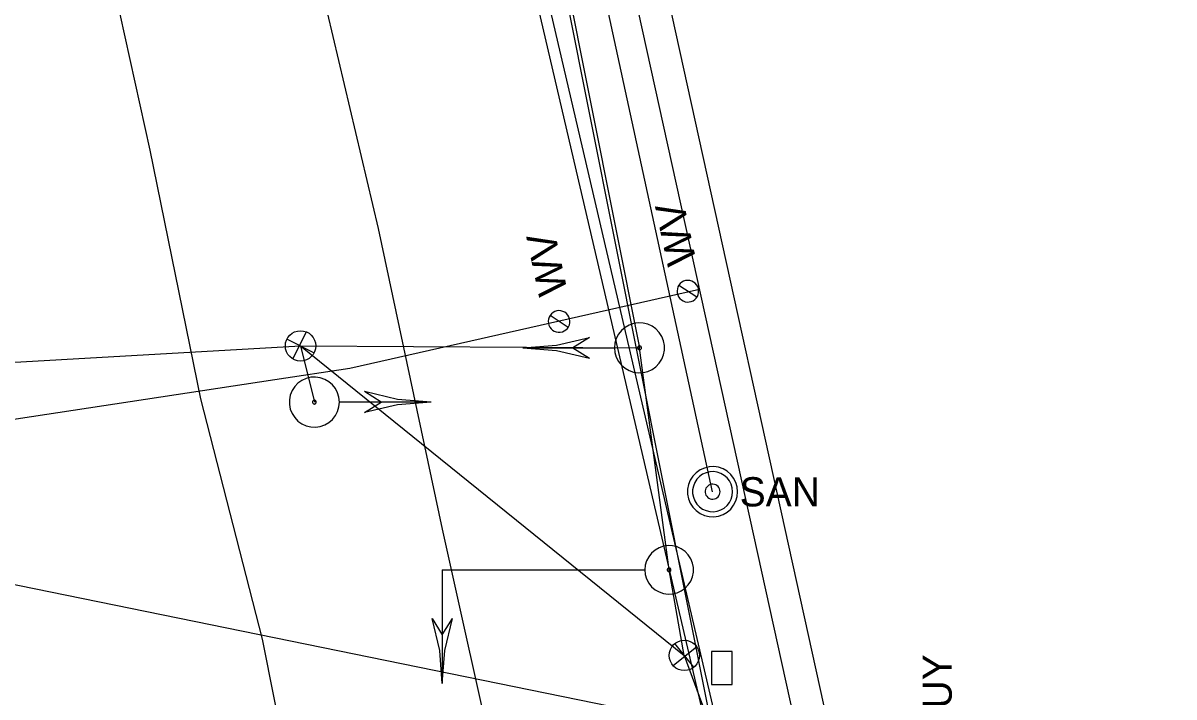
# Model space of a CAD drawing. Extents: x 596028 to 606371, y 330010 to 403088.
# Drawn here: x 604712 to 604863.7, y 339410.5 to 339499.3 of the extents above; entities that cross this region are included whole.
import ezdxf

# ---------------------------------------------------------------- set-up
doc = ezdxf.new("R2010")
doc.units = 0
for name, color, linetype in [('E_SIG', 7, 'Continuous'), ('E_SIG_Conduit', 7, 'Continuous'), ('E_UTL_E_UG', 7, 'Continuous'), ('E_UTL_EGuyWire', 7, 'Continuous'), ('E_UTL_FO_MH', 7, 'Continuous'), ('E_UTL_FO_UG', 7, 'Continuous'), ('E_UTL_G_UG', 7, 'Continuous'), ('E_UTL_Overhead', 7, 'Continuous'), ('E_UTL_SAN_MH', 7, 'Continuous'), ('E_UTL_SAN_UG', 7, 'Continuous'), ('E_UTL_SAN_UG_MMSD', 7, 'Continuous'), ('E_UTL_W', 7, 'Continuous'), ('E_UTL_W_UG', 7, 'Continuous')]:
    doc.layers.add(name, color=color, linetype=linetype)

# ---------------------------------------------------------------- blocks, each defined once
blk = doc.blocks.new('_U330')
at = {"layer": 'E_SIG'}
for p, q in [((0, 6.1), (0, -6.1)), ((-6.09, 0.4), (6.1, 0.4))]:
    blk.add_line(p, q, dxfattribs=at)
blk.add_circle((0, 0.01), 6.1, dxfattribs=at)
blk = doc.blocks.new('_U331')
at = {"layer": 'E_SIG'}
for p, q in [((0, 6.1), (0, -6.1)), ((-6.09, 0.4), (6.1, 0.4))]:
    blk.add_line(p, q, dxfattribs=at)
blk.add_circle((0, 0.01), 6.1, dxfattribs=at)

msp = doc.modelspace()

# ---------------------------------------------------------------- linework, layer by layer
at = {"layer": 'E_SIG'}
for points in [[(604789.97, 339456.48), (604790.03, 339455.86), (604790.21, 339455.26), (604790.49, 339454.7), (604790.88, 339454.2), (604791.36, 339453.79), (604791.9, 339453.48), (604792.49, 339453.27), (604793.11, 339453.19), (604793.74, 339453.22), (604794.35, 339453.36), (604794.92, 339453.62), (604795.43, 339453.99), (604795.86, 339454.44), (604796.2, 339454.97), (604796.44, 339455.55), (604796.55, 339456.17), (604796.55, 339456.8), (604796.44, 339457.41), (604796.2, 339457.99), (604795.86, 339458.52), (604795.43, 339458.98), (604794.92, 339459.34), (604794.35, 339459.6), (604793.74, 339459.75), (604793.11, 339459.78), (604792.49, 339459.69), (604791.9, 339459.48), (604791.36, 339459.17), (604790.88, 339458.76), (604790.49, 339458.27), (604790.21, 339457.71), (604790.03, 339457.11), (604789.97, 339456.48)], [(604777.87, 339456.48), (604782.32, 339456.83), (604786.67, 339457.86)], [(604786.67, 339457.85), (604784.47, 339456.48)], [(604748.6, 339456.73), (604750.42, 339449.33)], [(604777.87, 339456.48), (604789.91, 339456.48)], [(604777.87, 339456.48), (604782.32, 339456.14), (604786.67, 339455.11)], [(604784.47, 339456.48), (604786.67, 339455.11)], [(604793.02, 339456.48), (604793.02, 339456.43), (604793.04, 339456.39), (604793.06, 339456.35), (604793.09, 339456.31), (604793.12, 339456.28), (604793.16, 339456.25), (604793.21, 339456.24), (604793.26, 339456.23), (604793.31, 339456.23), (604793.35, 339456.24), (604793.4, 339456.26), (604793.43, 339456.29), (604793.47, 339456.33), (604793.49, 339456.37), (604793.51, 339456.41), (604793.52, 339456.46), (604793.52, 339456.51), (604793.51, 339456.55), (604793.49, 339456.6), (604793.47, 339456.64), (604793.43, 339456.67), (604793.4, 339456.7), (604793.35, 339456.72), (604793.31, 339456.73), (604793.26, 339456.73), (604793.21, 339456.73), (604793.16, 339456.71), (604793.12, 339456.69), (604793.09, 339456.66), (604793.06, 339456.62), (604793.04, 339456.58), (604793.02, 339456.53), (604793.02, 339456.48)], [(604753.72, 339449.33), (604753.66, 339449.96), (604753.48, 339450.56), (604753.2, 339451.11), (604752.81, 339451.61), (604752.34, 339452.02), (604751.79, 339452.33), (604751.2, 339452.54), (604750.58, 339452.63), (604749.95, 339452.6), (604749.34, 339452.45), (604748.77, 339452.19), (604748.26, 339451.82), (604747.83, 339451.37), (604747.49, 339450.84), (604747.25, 339450.26), (604747.14, 339449.64), (604747.14, 339449.02), (604747.25, 339448.4), (604747.49, 339447.82), (604747.83, 339447.29), (604748.26, 339446.84), (604748.77, 339446.47), (604749.34, 339446.21), (604749.95, 339446.06), (604750.58, 339446.03), (604751.2, 339446.12), (604751.79, 339446.33), (604752.34, 339446.64), (604752.81, 339447.05), (604753.2, 339447.55), (604753.48, 339448.1), (604753.66, 339448.71), (604753.72, 339449.33)], [(604750.67, 339449.33), (604750.67, 339449.38), (604750.66, 339449.42), (604750.63, 339449.47), (604750.6, 339449.5), (604750.57, 339449.54), (604750.53, 339449.56), (604750.48, 339449.58), (604750.43, 339449.58), (604750.39, 339449.58), (604750.34, 339449.57), (604750.3, 339449.55), (604750.26, 339449.52), (604750.22, 339449.49), (604750.2, 339449.45), (604750.18, 339449.4), (604750.17, 339449.35), (604750.17, 339449.31), (604750.18, 339449.26), (604750.2, 339449.21), (604750.22, 339449.17), (604750.26, 339449.14), (604750.3, 339449.11), (604750.34, 339449.09), (604750.39, 339449.08), (604750.43, 339449.08), (604750.48, 339449.09), (604750.53, 339449.1), (604750.57, 339449.13), (604750.6, 339449.16), (604750.63, 339449.19), (604750.66, 339449.24), (604750.67, 339449.28), (604750.67, 339449.33)], [(604765.82, 339449.33), (604753.78, 339449.33)], [(604765.82, 339449.33), (604761.37, 339449.68), (604757.02, 339450.71)], [(604759.22, 339449.33), (604757.02, 339450.71)], [(604765.82, 339449.33), (604761.37, 339448.98), (604757.02, 339447.96)], [(604757.02, 339447.96), (604759.22, 339449.33)], [(604793.97, 339427.23), (604794.02, 339426.62), (604794.2, 339426.04), (604794.48, 339425.5), (604794.85, 339425.02), (604795.31, 339424.62), (604795.84, 339424.32), (604796.41, 339424.12), (604797.02, 339424.03), (604797.63, 339424.06), (604798.22, 339424.2), (604798.77, 339424.46), (604799.27, 339424.81), (604799.69, 339425.25), (604800.02, 339425.76), (604800.24, 339426.33), (604800.36, 339426.93), (604800.36, 339427.54), (604800.24, 339428.13), (604800.02, 339428.7), (604799.69, 339429.21), (604799.27, 339429.65), (604798.77, 339430), (604798.22, 339430.26), (604797.63, 339430.4), (604797.02, 339430.43), (604796.41, 339430.34), (604795.84, 339430.14), (604795.31, 339429.84), (604794.85, 339429.44), (604794.48, 339428.96), (604794.2, 339428.42), (604794.02, 339427.84), (604793.97, 339427.23)], [(604767.28, 339427.23), (604793.91, 339427.23)], [(604767.28, 339427.23), (604767.28, 339412.28)], [(604774.75, 339427.23), (604774.75, 339427.23)], [(604796.92, 339427.23), (604796.93, 339427.18), (604796.94, 339427.14), (604796.96, 339427.1), (604796.99, 339427.06), (604797.03, 339427.03), (604797.07, 339427.01), (604797.11, 339426.99), (604797.16, 339426.99), (604797.2, 339426.99), (604797.25, 339427), (604797.29, 339427.02), (604797.33, 339427.05), (604797.36, 339427.08), (604797.39, 339427.12), (604797.4, 339427.16), (604797.41, 339427.21), (604797.41, 339427.25), (604797.4, 339427.3), (604797.39, 339427.34), (604797.36, 339427.38), (604797.33, 339427.42), (604797.29, 339427.44), (604797.25, 339427.46), (604797.2, 339427.47), (604797.16, 339427.48), (604797.11, 339427.47), (604797.07, 339427.45), (604797.03, 339427.43), (604796.99, 339427.4), (604796.96, 339427.36), (604796.94, 339427.32), (604796.93, 339427.28), (604796.92, 339427.23)], [(604799.17, 339415.97), (604797.17, 339427.23)], [(604767.28, 339412.28), (604766.94, 339416.61), (604765.94, 339420.82)], [(604765.94, 339420.82), (604767.28, 339418.69)], [(604767.28, 339412.28), (604767.61, 339416.61), (604768.61, 339420.82)], [(604767.28, 339418.69), (604768.61, 339420.82)]]:
    msp.add_lwpolyline(points, dxfattribs=at)
at = {"layer": 'E_SIG_Conduit'}
msp.add_line((604797.17, 339427.23), (604793.27, 339456.48), dxfattribs=at)
for points in [[(604685.54, 339453.14), (604748.6, 339456.73)], [(604748.6, 339456.73), (604799.17, 339415.97)], [(604799.17, 339415.97), (604805.96, 339397.51)]]:
    msp.add_lwpolyline(points, dxfattribs=at)
at = {"layer": 'E_UTL_E_UG'}
msp.add_lwpolyline([(604784.34, 339222.62), (604775.95, 339262.38), (604768.41, 339297.38), (604762.12, 339328.3), (604755.94, 339361.93), (604755.64, 339363.5), (604751.45, 339378.59), (604743.59, 339418.09), (604735.46, 339449.75), (604728.77, 339482.52), (604722.85, 339509.42)], dxfattribs=at)
at = {"layer": 'E_UTL_FO_MH'}
msp.add_lwpolyline([(604805.48, 339412.14), (604805.48, 339416.47), (604802.73, 339416.47), (604802.73, 339412.14)], close=True, dxfattribs=at)
at = {"layer": 'E_UTL_FO_UG'}
for points in [[(604780.2, 339521.92), (604793.27, 339456.48)], [(604685.54, 339453.14), (604748.6, 339456.73), (604793.27, 339456.48)], [(604793.27, 339456.48), (604793.27, 339456.48)]]:
    msp.add_lwpolyline(points, dxfattribs=at)
at = {"layer": 'E_UTL_G_UG'}
msp.add_lwpolyline([(604814.85, 339218.78), (604810.09, 339242.37), (604799.43, 339289.54), (604793.26, 339314.06), (604787.02, 339344.67), (604774.66, 339399.62), (604767.29, 339432.61), (604758.85, 339472.19), (604751.42, 339503.86)], dxfattribs=at)
at = {"layer": 'E_UTL_Overhead'}
msp.add_line((604818.92, 339403.26), (604792.43, 339523.66), dxfattribs=at)
msp.add_lwpolyline([(604487.17, 339458.6), (604640.66, 339429.67), (604683.98, 339430.78), (604818.92, 339403.26), (604974.13, 339363.63), (605153.06, 339361.47)], dxfattribs=at)
at = {"layer": 'E_UTL_SAN_MH'}
for points in [[(604806.2, 339437.53), (604806.14, 339438.16), (604805.96, 339438.76), (604805.67, 339439.32), (604805.29, 339439.81), (604804.81, 339440.22), (604804.27, 339440.53), (604803.68, 339440.74), (604803.05, 339440.83), (604802.43, 339440.8), (604801.82, 339440.65), (604801.25, 339440.39), (604800.74, 339440.03), (604800.3, 339439.57), (604799.96, 339439.04), (604799.73, 339438.46), (604799.61, 339437.85), (604799.61, 339437.22), (604799.73, 339436.6), (604799.96, 339436.02), (604800.3, 339435.49), (604800.74, 339435.04), (604801.25, 339434.67), (604801.82, 339434.41), (604802.43, 339434.27), (604803.05, 339434.24), (604803.68, 339434.32), (604804.27, 339434.53), (604804.81, 339434.84), (604805.29, 339435.25), (604805.67, 339435.75), (604805.96, 339436.31), (604806.14, 339436.91), (604806.2, 339437.53)], [(604805.54, 339437.53), (604805.49, 339438.03), (604805.35, 339438.51), (604805.12, 339438.96), (604804.81, 339439.35), (604804.43, 339439.68), (604803.99, 339439.93), (604803.52, 339440.1), (604803.02, 339440.17), (604802.52, 339440.14), (604802.03, 339440.03), (604801.58, 339439.82), (604801.17, 339439.53), (604800.82, 339439.16), (604800.55, 339438.74), (604800.36, 339438.28), (604800.27, 339437.78), (604800.27, 339437.28), (604800.36, 339436.79), (604800.55, 339436.32), (604800.82, 339435.9), (604801.17, 339435.54), (604801.58, 339435.25), (604802.03, 339435.04), (604802.52, 339434.92), (604803.02, 339434.89), (604803.52, 339434.97), (604803.99, 339435.13), (604804.43, 339435.38), (604804.81, 339435.71), (604805.12, 339436.1), (604805.35, 339436.55), (604805.49, 339437.03), (604805.54, 339437.53)], [(604803.89, 339437.53), (604803.87, 339437.72), (604803.82, 339437.9), (604803.73, 339438.07), (604803.61, 339438.22), (604803.47, 339438.34), (604803.31, 339438.43), (604803.13, 339438.49), (604802.94, 339438.52), (604802.76, 339438.51), (604802.57, 339438.47), (604802.4, 339438.39), (604802.25, 339438.28), (604802.12, 339438.14), (604802.02, 339437.99), (604801.95, 339437.81), (604801.91, 339437.63), (604801.91, 339437.44), (604801.95, 339437.25), (604802.02, 339437.08), (604802.12, 339436.92), (604802.25, 339436.78), (604802.4, 339436.67), (604802.57, 339436.6), (604802.76, 339436.55), (604802.94, 339436.54), (604803.13, 339436.57), (604803.31, 339436.63), (604803.47, 339436.73), (604803.61, 339436.85), (604803.73, 339437), (604803.82, 339437.16), (604803.87, 339437.34), (604803.89, 339437.53)]]:
    msp.add_lwpolyline(points, dxfattribs=at)
at = {"layer": 'E_UTL_SAN_UG'}
msp.add_line((604802.9, 339437.53), (604748.39, 339688.17), dxfattribs=at)
at = {"layer": 'E_UTL_SAN_UG_MMSD'}
msp.add_line((604854.51, 339147.21), (604642.2, 340212.1), dxfattribs=at)
at = {"layer": 'E_UTL_W'}
for points in [[(604799.34, 339465.33), (604799.08, 339465.25), (604798.85, 339465.12), (604798.64, 339464.95), (604798.46, 339464.74), (604798.33, 339464.5), (604798.25, 339464.25), (604798.21, 339463.98), (604798.23, 339463.71), (604798.3, 339463.45), (604798.42, 339463.2), (604798.58, 339462.98), (604798.78, 339462.8), (604799.01, 339462.66), (604799.26, 339462.56), (604799.53, 339462.51), (604799.8, 339462.52), (604800.07, 339462.58), (604800.32, 339462.68), (604800.54, 339462.83), (604800.73, 339463.02), (604800.89, 339463.25), (604801, 339463.5), (604801.05, 339463.76), (604801.06, 339464.03), (604801.02, 339464.3), (604800.93, 339464.55), (604800.79, 339464.79), (604800.6, 339464.99), (604800.39, 339465.15), (604800.14, 339465.27), (604799.88, 339465.34), (604799.61, 339465.36), (604799.34, 339465.33)], [(604800.84, 339463.16), (604798.44, 339464.71)], [(604782.37, 339461.35), (604782.12, 339461.26), (604781.88, 339461.14), (604781.67, 339460.96), (604781.49, 339460.76), (604781.36, 339460.52), (604781.28, 339460.26), (604781.25, 339459.99), (604781.26, 339459.72), (604781.33, 339459.46), (604781.45, 339459.22), (604781.61, 339459), (604781.81, 339458.81), (604782.04, 339458.67), (604782.29, 339458.58), (604782.56, 339458.53), (604782.83, 339458.53), (604783.1, 339458.59), (604783.35, 339458.7), (604783.57, 339458.85), (604783.77, 339459.04), (604783.92, 339459.26), (604784.03, 339459.51), (604784.09, 339459.77), (604784.09, 339460.05), (604784.05, 339460.31), (604783.96, 339460.57), (604783.82, 339460.8), (604783.64, 339461), (604783.42, 339461.16), (604783.18, 339461.28), (604782.91, 339461.36), (604782.64, 339461.38), (604782.37, 339461.35)], [(604783.87, 339459.17), (604781.48, 339460.73)]]:
    msp.add_lwpolyline(points, dxfattribs=at)
at = {"layer": 'E_UTL_W_UG'}
for points in [[(604799.27, 339472.85), (604724.3, 339813.08)], [(604805.77, 339390.57), (604775.12, 339521.94), (604713.1, 339806.92)], [(604807.23, 339390.91), (604776.58, 339522.27), (604714.57, 339807.24)], [(604834.02, 339335.63), (604819.48, 339381.14), (604799.27, 339472.85)], [(604673.41, 339461.4), (604686.54, 339443.41), (604745.2, 339452.3), (604755.11, 339453.8), (604801.17, 339464.21)]]:
    msp.add_lwpolyline(points, dxfattribs=at)

# ---------------------------------------------------------------- block references
at = {"layer": 'E_SIG_Conduit', "xscale": 0.32808333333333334}
for name, p, yscale, rotation in [('_U331', (604748.6, 339456.73), 0.3280833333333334, 62.91979054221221), ('_U330', (604799.17, 339415.97), 0.32808333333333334, -141.2392746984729)]:
    msp.add_blockref(name, p, dxfattribs=dict(at, yscale=yscale, rotation=rotation))

# ---------------------------------------------------------------- texts
at = {"layer": 'E_UTL_EGuyWire'}
msp.add_text('GUY', height=3.85, rotation=90, dxfattribs=at).set_placement((604834.41, 339404.97))
at = {"layer": 'E_UTL_SAN_MH'}
msp.add_text('SAN', height=3.849, dxfattribs=at).set_placement((604806.46, 339435.59))
at = {"layer": 'E_UTL_W'}
for p in [(604800.78, 339467.82), (604783.81, 339463.84)]:
    msp.add_text('WV', height=3.85, rotation=101.9808, dxfattribs=at).set_placement(p)

doc.saveas('drawing.dxf')
